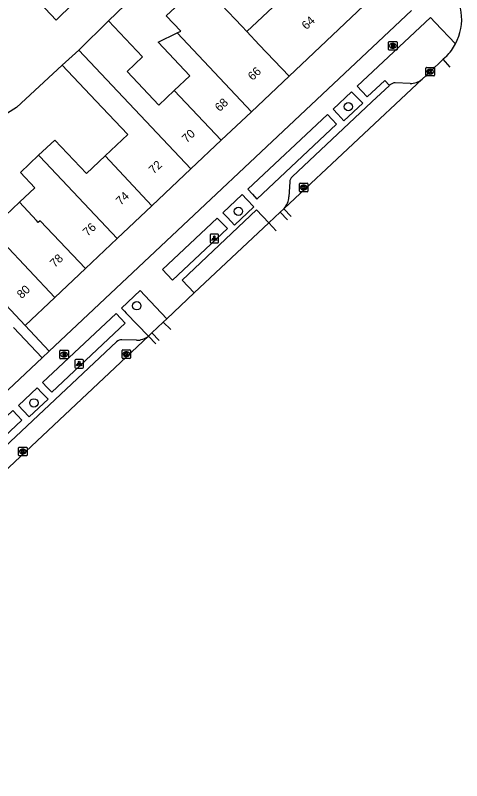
# Model space of a CAD drawing. Extents: x 162347 to 162868, y 381221 to 381813.
# Drawn here: x 162602.8 to 162655.1, y 381237 to 381326.8 of the extents above; entities that cross this region are included whole.
import ezdxf

# ---------------------------------------------------------------- set-up
doc = ezdxf.new("R2010")
doc.units = 0
for name, color, linetype in [('IMGEO_Boom', 7, 'Continuous'), ('IMGEO_Brandkraan', 7, 'Continuous'), ('IMGEO_Kolk', 7, 'Continuous'), ('IMGEO_Lichtpunt', 7, 'Continuous'), ('IMGEO_Pand', 7, 'Continuous'), ('IMGEO_Pand_nummerreeks', 7, 'Continuous'), ('IMGEO_Pand_vergunning_verleend', 7, 'Continuous'), ('IMGEO_Parkeervlak_open', 7, 'Continuous'), ('IMGEO_Rijbaan_lokaal_gesloten', 7, 'Continuous'), ('IMGEO_Rijbaan_lokaal_open', 7, 'Continuous'), ('IMGEO_Voetpad_open', 7, 'Continuous')]:
    doc.layers.add(name, color=color, linetype=linetype)

msp = doc.modelspace()

# ---------------------------------------------------------------- linework, layer by layer
at = {"layer": 'IMGEO_Boom'}
for centre in [(162641.839, 381316.04), (162628.943, 381303.772), (162617.021, 381292.697), (162604.944, 381281.303)]:
    msp.add_circle(centre, 0.489, dxfattribs=at)
at = {"layer": 'IMGEO_Brandkraan'}
for p, q in [((162646.551, 381322.756), (162646.551, 381323.608)), ((162646.626, 381323.682), (162647.478, 381323.682)), ((162647.039, 381323.462), (162647.064, 381323.462)), ((162647.552, 381323.608), (162647.552, 381322.756)), ((162647.478, 381322.682), (162646.626, 381322.682)), ((162647.062, 381322.902), (162647.037, 381322.902)), ((162607.99, 381286.551), (162607.99, 381287.403)), ((162608.065, 381287.477), (162608.917, 381287.477)), ((162608.478, 381287.257), (162608.503, 381287.257)), ((162608.991, 381287.403), (162608.991, 381286.551)), ((162608.917, 381286.477), (162608.065, 381286.477)), ((162608.501, 381286.697), (162608.476, 381286.697))]:
    msp.add_line(p, q, dxfattribs=at)
for points in [[(162646.551, 381322.756), (162646.551, 381323.608)], [(162646.626, 381323.682), (162647.478, 381323.682)], [(162646.899, 381323.382), (162646.899, 381322.982), (162647.112, 381322.982)], [(162647.13, 381323.382), (162646.899, 381323.382)], [(162647.078, 381323.301), (162647.024, 381323.301), (162647.024, 381323.225)], [(162647.024, 381323.225), (162647.077, 381323.225)], [(162647.086, 381323.149), (162647.024, 381323.149), (162647.024, 381323.068)], [(162647.552, 381323.608), (162647.552, 381322.756)], [(162647.478, 381322.682), (162646.626, 381322.682)], [(162647.024, 381323.068), (162647.086, 381323.068)], [(162607.99, 381286.551), (162607.99, 381287.403)], [(162608.065, 381287.477), (162608.917, 381287.477)], [(162608.338, 381287.177), (162608.338, 381286.777), (162608.551, 381286.777)], [(162608.569, 381287.177), (162608.338, 381287.177)], [(162608.991, 381287.403), (162608.991, 381286.551)], [(162608.917, 381286.477), (162608.065, 381286.477)], [(162608.517, 381287.096), (162608.463, 381287.096), (162608.463, 381287.02)], [(162608.463, 381287.02), (162608.516, 381287.02)], [(162608.525, 381286.944), (162608.463, 381286.944), (162608.463, 381286.863)], [(162608.463, 381286.863), (162608.525, 381286.863)]]:
    msp.add_lwpolyline(points, dxfattribs=at)
for centre, radius, start, end in [((162646.628, 381323.606), 0.0765, 91.55205, 178.44795), ((162646.628, 381323.606), 0.0765, 91.55205, 178.44795), ((162647.079, 381323.263), 0.0379, 267.82845, 90.93552), ((162647.087, 381323.108), 0.0404, 269.87594, 90.50774), ((162647.134, 381323.237), 0.145, 59.4692, 91.53667), ((162647.159, 381323.284), 0.0922, 285.51372, 58.15012), ((162647.164, 381323.092), 0.105, 301.31148, 78.98903), ((162647.476, 381323.606), 0.0765, 1.55205, 88.44795), ((162647.476, 381323.606), 0.0765, 1.55205, 88.44795), ((162646.628, 381322.758), 0.0765, 181.55205, 268.44795), ((162646.628, 381322.758), 0.0765, 181.55205, 268.44795), ((162647.118, 381323.233), 0.251, 268.66757, 293.53466), ((162647.476, 381322.758), 0.0765, 271.55205, 358.44795), ((162647.476, 381322.758), 0.0765, 271.55205, 358.44795), ((162608.067, 381287.401), 0.0765, 91.55205, 178.44795), ((162608.067, 381287.401), 0.0765, 91.55205, 178.44795), ((162608.573, 381287.032), 0.145, 59.4692, 91.53667), ((162608.915, 381287.401), 0.0765, 1.55205, 88.44795), ((162608.915, 381287.401), 0.0765, 1.55205, 88.44795), ((162608.067, 381286.553), 0.0765, 181.55205, 268.44795), ((162608.067, 381286.553), 0.0765, 181.55205, 268.44795), ((162608.518, 381287.058), 0.0379, 267.82845, 90.93552), ((162608.526, 381286.903), 0.0404, 269.87594, 90.50774), ((162608.557, 381287.028), 0.251, 268.66757, 293.53466), ((162608.598, 381287.079), 0.0922, 285.51372, 58.15012), ((162608.603, 381286.887), 0.105, 301.31148, 78.98903), ((162608.915, 381286.553), 0.0765, 271.55205, 358.44795), ((162608.915, 381286.553), 0.0765, 271.55205, 358.44795)]:
    msp.add_arc(centre, radius, start, end, dxfattribs=at)
for centre, major_axis, ratio, start_param, end_param in [((162647.038, 381323.182), (-0.387, 0.002), 0.722429, 4.712389, 7.853982), ((162647.063, 381323.182), (-0.39, 0.002), 0.717154, 1.570796, 4.712389), ((162608.477, 381286.977), (-0.387, 0.002), 0.722429, 4.712389, 7.853982), ((162608.502, 381286.977), (-0.39, 0.002), 0.717154, 1.570796, 4.712389)]:
    msp.add_ellipse(centre, major_axis=major_axis, ratio=ratio, start_param=start_param, end_param=end_param, dxfattribs=at)
at = {"layer": 'IMGEO_Kolk'}
for p, q in [((162650.934, 381319.721), (162650.934, 381320.573)), ((162651.009, 381320.647), (162651.861, 381320.647)), ((162651.422, 381320.427), (162651.447, 381320.427)), ((162651.935, 381320.573), (162651.935, 381319.721)), ((162651.861, 381319.647), (162651.009, 381319.647)), ((162651.445, 381319.867), (162651.42, 381319.867)), ((162636.099, 381306.141), (162636.099, 381306.993)), ((162636.174, 381307.067), (162637.026, 381307.067)), ((162637.1, 381306.993), (162637.1, 381306.141)), ((162637.026, 381306.067), (162636.174, 381306.067)), ((162636.61, 381306.287), (162636.585, 381306.287)), ((162636.587, 381306.847), (162636.612, 381306.847)), ((162615.297, 381286.599), (162615.297, 381287.451)), ((162615.372, 381287.525), (162616.224, 381287.525)), ((162615.785, 381287.305), (162615.81, 381287.305)), ((162616.298, 381287.451), (162616.298, 381286.599)), ((162616.224, 381286.525), (162615.372, 381286.525)), ((162615.808, 381286.745), (162615.783, 381286.745)), ((162603.157, 381275.168), (162603.157, 381276.02)), ((162603.232, 381276.094), (162604.084, 381276.094)), ((162603.645, 381275.874), (162603.67, 381275.874)), ((162604.158, 381276.02), (162604.158, 381275.168)), ((162604.084, 381275.094), (162603.232, 381275.094)), ((162603.668, 381275.314), (162603.643, 381275.314))]:
    msp.add_line(p, q, dxfattribs=at)
for points in [[(162650.934, 381319.721), (162650.934, 381320.573)], [(162651.009, 381320.647), (162651.861, 381320.647)], [(162651.935, 381320.573), (162651.935, 381319.721)], [(162651.861, 381319.647), (162651.009, 381319.647)], [(162651.255, 381320.347), (162651.378, 381320.347), (162651.378, 381320.196), (162651.508, 381320.347), (162651.672, 381320.347), (162651.526, 381320.196), (162651.679, 381319.947), (162651.527, 381319.947), (162651.442, 381320.111), (162651.378, 381320.044), (162651.378, 381319.947), (162651.255, 381319.947), (162651.255, 381320.347)], [(162636.099, 381306.141), (162636.099, 381306.993)], [(162636.174, 381307.067), (162637.026, 381307.067)], [(162637.1, 381306.993), (162637.1, 381306.141)], [(162637.026, 381306.067), (162636.174, 381306.067)], [(162636.42, 381306.767), (162636.543, 381306.767), (162636.543, 381306.616), (162636.673, 381306.767), (162636.837, 381306.767), (162636.691, 381306.616), (162636.844, 381306.367), (162636.692, 381306.367), (162636.607, 381306.531), (162636.543, 381306.464), (162636.543, 381306.367), (162636.42, 381306.367), (162636.42, 381306.767)], [(162615.297, 381286.599), (162615.297, 381287.451)], [(162615.372, 381287.525), (162616.224, 381287.525)], [(162615.618, 381287.225), (162615.741, 381287.225), (162615.741, 381287.074), (162615.871, 381287.225), (162616.035, 381287.225), (162615.889, 381287.074), (162616.042, 381286.825), (162615.89, 381286.825), (162615.805, 381286.989), (162615.741, 381286.922), (162615.741, 381286.825), (162615.618, 381286.825), (162615.618, 381287.225)], [(162616.298, 381287.451), (162616.298, 381286.599)], [(162616.224, 381286.525), (162615.372, 381286.525)], [(162603.157, 381275.168), (162603.157, 381276.02)], [(162603.232, 381276.094), (162604.084, 381276.094)], [(162603.478, 381275.794), (162603.601, 381275.794), (162603.601, 381275.643), (162603.731, 381275.794), (162603.895, 381275.794), (162603.749, 381275.643), (162603.902, 381275.394), (162603.75, 381275.394), (162603.665, 381275.558), (162603.601, 381275.491), (162603.601, 381275.394), (162603.478, 381275.394), (162603.478, 381275.794)], [(162604.158, 381276.02), (162604.158, 381275.168)], [(162604.084, 381275.094), (162603.232, 381275.094)]]:
    msp.add_lwpolyline(points, dxfattribs=at)
for centre, start, end in [((162651.011, 381320.571), 91.55205, 178.44795), ((162651.011, 381320.571), 91.55205, 178.44795), ((162651.859, 381320.571), 1.55205, 88.44795), ((162651.859, 381320.571), 1.55205, 88.44795), ((162651.011, 381319.723), 181.55205, 268.44795), ((162651.011, 381319.723), 181.55205, 268.44795), ((162651.859, 381319.723), 271.55205, 358.44795), ((162651.859, 381319.723), 271.55205, 358.44795), ((162636.176, 381306.991), 91.55205, 178.44795), ((162636.176, 381306.991), 91.55205, 178.44795), ((162637.024, 381306.991), 1.55205, 88.44795), ((162637.024, 381306.991), 1.55205, 88.44795), ((162636.176, 381306.143), 181.55205, 268.44795), ((162636.176, 381306.143), 181.55205, 268.44795), ((162637.024, 381306.143), 271.55205, 358.44795), ((162637.024, 381306.143), 271.55205, 358.44795), ((162615.374, 381287.449), 91.55205, 178.44795), ((162615.374, 381287.449), 91.55205, 178.44795), ((162616.222, 381287.449), 1.55205, 88.44795), ((162616.222, 381287.449), 1.55205, 88.44795), ((162615.374, 381286.601), 181.55205, 268.44795), ((162615.374, 381286.601), 181.55205, 268.44795), ((162616.222, 381286.601), 271.55205, 358.44795), ((162616.222, 381286.601), 271.55205, 358.44795), ((162603.234, 381276.018), 91.55205, 178.44795), ((162603.234, 381276.018), 91.55205, 178.44795), ((162604.082, 381276.018), 1.55205, 88.44795), ((162604.082, 381276.018), 1.55205, 88.44795), ((162603.234, 381275.17), 181.55205, 268.44795), ((162603.234, 381275.17), 181.55205, 268.44795), ((162604.082, 381275.17), 271.55205, 358.44795), ((162604.082, 381275.17), 271.55205, 358.44795)]:
    msp.add_arc(centre, 0.0765, start, end, dxfattribs=at)
for centre, major_axis, ratio, start_param, end_param in [((162651.421, 381320.147), (-0.387, 0.002), 0.722429, 4.712389, 7.853982), ((162651.446, 381320.147), (-0.39, 0.002), 0.717154, 1.570796, 4.712389), ((162636.586, 381306.567), (-0.387, 0.002), 0.722429, 4.712389, 7.853982), ((162636.611, 381306.567), (-0.39, 0.002), 0.717154, 1.570796, 4.712389), ((162615.784, 381287.025), (-0.387, 0.002), 0.722429, 4.712389, 7.853982), ((162615.809, 381287.025), (-0.39, 0.002), 0.717154, 1.570796, 4.712389), ((162603.644, 381275.594), (-0.387, 0.002), 0.722429, 4.712389, 7.853982), ((162603.669, 381275.594), (-0.39, 0.002), 0.717154, 1.570796, 4.712389)]:
    msp.add_ellipse(centre, major_axis=major_axis, ratio=ratio, start_param=start_param, end_param=end_param, dxfattribs=at)
at = {"layer": 'IMGEO_Lichtpunt'}
for p, q in [((162625.621, 381300.984), (162625.621, 381300.177)), ((162625.621, 381300.984), (162625.621, 381300.177)), ((162626.523, 381301.079), (162625.715, 381301.079)), ((162626.523, 381301.079), (162625.715, 381301.079)), ((162626.617, 381300.177), (162626.617, 381300.984)), ((162626.617, 381300.177), (162626.617, 381300.984)), ((162625.715, 381300.083), (162626.523, 381300.083)), ((162625.715, 381300.083), (162626.523, 381300.083)), ((162609.769, 381286.292), (162609.769, 381285.485)), ((162609.769, 381286.292), (162609.769, 381285.485)), ((162610.671, 381286.387), (162609.863, 381286.387)), ((162610.671, 381286.387), (162609.863, 381286.387)), ((162610.765, 381285.485), (162610.765, 381286.292)), ((162610.765, 381285.485), (162610.765, 381286.292)), ((162609.863, 381285.391), (162610.671, 381285.391)), ((162609.863, 381285.391), (162610.671, 381285.391))]:
    msp.add_line(p, q, dxfattribs=at)
for points in [[(162625.995, 381300.648), (162626.034, 381300.62), (162625.846, 381300.358), (162625.808, 381300.385), (162625.995, 381300.648)], [(162626.207, 381300.62), (162626.245, 381300.647), (162626.432, 381300.385), (162626.393, 381300.357), (162626.207, 381300.62)], [(162626.097, 381300.6), (162626.144, 381300.6), (162626.144, 381300.278), (162626.097, 381300.278), (162626.097, 381300.6)], [(162610.143, 381285.956), (162610.182, 381285.928), (162609.994, 381285.666), (162609.956, 381285.693), (162610.143, 381285.956)], [(162610.245, 381285.908), (162610.292, 381285.908), (162610.292, 381285.586), (162610.245, 381285.586), (162610.245, 381285.908)], [(162610.355, 381285.928), (162610.393, 381285.955), (162610.58, 381285.693), (162610.541, 381285.665), (162610.355, 381285.928)]]:
    msp.add_lwpolyline(points, dxfattribs=at)
for centre in [(162626.12, 381300.782), (162610.268, 381286.09)]:
    msp.add_circle(centre, 0.0994, dxfattribs=at)
for centre, start, end in [((162625.715, 381300.984), 90, 180), ((162625.715, 381300.984), 90, 180), ((162626.523, 381300.984), 0, 90), ((162626.523, 381300.984), 0, 90), ((162625.715, 381300.177), 180, 270), ((162625.715, 381300.177), 180, 270), ((162626.523, 381300.177), 270, 0), ((162626.523, 381300.177), 270, 360), ((162609.863, 381286.292), 90, 180), ((162609.863, 381286.292), 90, 180), ((162610.671, 381286.292), 0, 90), ((162610.671, 381286.292), 0, 90), ((162609.863, 381285.485), 180, 270), ((162609.863, 381285.485), 180, 270), ((162610.671, 381285.485), 270, 0), ((162610.671, 381285.485), 270, 360)]:
    msp.add_arc(centre, 0.0946, start, end, dxfattribs=at)
at = {"layer": 'IMGEO_Pand'}
for points in [[(162629.938, 381324.841), (162632.97, 381327.703), (162633.243, 381329.819), (162626.751, 381330.658), (162626.959, 381332.52), (162627.514, 381337.489), (162634.853, 381336.669), (162636.515, 381336.483), (162636.272, 381334.735), (162638.163, 381332.6), (162641.264, 381332.167), (162643.71, 381329.594), (162643.635, 381327.873), (162634.883, 381319.61)], [(162621.767, 381324.685), (162622.173, 381324.883), (162620.476, 381326.68), (162624.56, 381330.536), (162629.33, 381325.484), (162629.938, 381324.841)], [(162613.703, 381326.117), (162610.208, 381322.688)], [(162613.703, 381326.117), (162617.694, 381321.891), (162615.885, 381320.183), (162619.616, 381316.231), (162621.426, 381317.94)], [(162621.426, 381317.94), (162623.239, 381319.652), (162619.521, 381323.59), (162621.767, 381324.685)], [(162621.767, 381324.685), (162630.482, 381315.455)], [(162634.883, 381319.61), (162631.379, 381323.314), (162629.938, 381324.841)], [(162610.208, 381322.688), (162608.277, 381320.913)], [(162610.208, 381322.688), (162614.134, 381318.53), (162623.374, 381308.744)], [(162613.297, 381310.265), (162615.957, 381312.776), (162612.226, 381316.728), (162608.277, 381320.913)], [(162634.883, 381319.61), (162630.482, 381315.455)], [(162621.426, 381317.94), (162626.934, 381312.105)], [(162630.482, 381315.455), (162626.934, 381312.105)], [(162605.494, 381310.337), (162607.392, 381312.129), (162611.106, 381308.196), (162613.297, 381310.265)], [(162626.934, 381312.105), (162623.374, 381308.744)], [(162603.276, 381304.83), (162605.065, 381306.52), (162603.362, 381308.324), (162605.494, 381310.337)], [(162605.494, 381310.337), (162605.631, 381310.186), (162614.714, 381300.568)], [(162613.297, 381310.265), (162618.804, 381304.429)], [(162623.374, 381308.744), (162618.804, 381304.429)], [(162598.154, 381303.494), (162599.868, 381305.112), (162601.615, 381303.262), (162603.276, 381304.83)], [(162610.986, 381297.048), (162605.679, 381302.669), (162605.456, 381302.458), (162605.252, 381302.68), (162603.276, 381304.83)], [(162618.804, 381304.429), (162614.714, 381300.568)], [(162598.154, 381303.494), (162598.332, 381303.294), (162607.414, 381293.676)], [(162614.714, 381300.568), (162610.986, 381297.048)], [(162610.986, 381297.048), (162607.414, 381293.676)], [(162598.479, 381296.126), (162600.481, 381294.006), (162603.913, 381290.37)], [(162607.414, 381293.676), (162603.913, 381290.37)]]:
    msp.add_lwpolyline(points, dxfattribs=at)
at = {"layer": 'IMGEO_Pand_vergunning_verleend'}
msp.add_lwpolyline([(162603.052, 381331.009), (162603.77, 381331.681), (162613.666, 381340.953), (162618.167, 381336.158), (162608.281, 381326.876), (162607.559, 381326.199), (162603.052, 381331.009)], dxfattribs=at)
at = {"layer": 'IMGEO_Parkeervlak_open'}
for points in [[(162649.085, 381318.772), (162647.341, 381318.826)], [(162646.728, 381318.584), (162646.667, 381318.527)]]:
    msp.add_lwpolyline(points, dxfattribs=at)
for centre, radius, start, end in [((162647.287, 381318.065), 0.763, 85.95511, 137.1311), ((162649.197, 381320.726), 1.957, 266.70829, 311.09283)]:
    msp.add_arc(centre, radius, start, end, dxfattribs=at)
at = {"layer": 'IMGEO_Rijbaan_lokaal_gesloten'}
for points in [[(162652.983, 381321.602), (162651.435, 381320.147), (162650.484, 381319.251)], [(162653.774, 381320.694), (162652.983, 381321.602)], [(162650.484, 381319.251), (162634.298, 381304.099)], [(162634.298, 381304.099), (162634.271, 381304.074)], [(162634.271, 381304.074), (162635.132, 381303.165)], [(162632.497, 381302.404), (162623.772, 381294.193)], [(162632.497, 381302.404), (162633.362, 381301.5)], [(162623.772, 381294.193), (162620.553, 381291.162)], [(162620.553, 381291.162), (162620.131, 381290.766)], [(162621.016, 381289.891), (162620.131, 381290.766)], [(162618.404, 381289.14), (162564.022, 381238.062), (162562.871, 381236.993)], [(162619.267, 381288.247), (162618.404, 381289.14)]]:
    msp.add_lwpolyline(points, dxfattribs=at)
at = {"layer": 'IMGEO_Rijbaan_lokaal_open'}
for points in [[(162653.341, 381321.938), (162652.983, 381321.602)], [(162633.847, 381303.674), (162632.524, 381302.429)], [(162634.271, 381304.074), (162633.847, 381303.674)], [(162634.718, 381302.775), (162633.847, 381303.674)], [(162632.524, 381302.429), (162632.497, 381302.404)], [(162620.131, 381290.766), (162618.802, 381289.515)], [(162618.802, 381289.515), (162618.404, 381289.14)], [(162619.656, 381288.613), (162618.802, 381289.515)]]:
    msp.add_lwpolyline(points, dxfattribs=at)
for centre, radius, start, end in [((162648.834, 381326.349), 6.306, 332.11689, 41.86905), ((162648.797, 381326.375), 6.351, 315.68485, 332.06956)]:
    msp.add_arc(centre, radius, start, end, dxfattribs=at)
at = {"layer": 'IMGEO_Voetpad_open'}
for points in [[(162630.047, 381341.818), (162613.703, 381326.117)], [(162606.75, 381287.36), (162649.241, 381327.313)], [(162654.408, 381323.4), (162652.04, 381325.932), (162651.494, 381326.516), (162642.884, 381318.432), (162643.43, 381317.847), (162644.045, 381317.188), (162646.11, 381319.125), (162646.667, 381318.527)], [(162608.277, 381320.913), (162602.909, 381315.953), (162601.13, 381314.823)], [(162646.667, 381318.527), (162644.602, 381316.591), (162635.242, 381307.816)], [(162643.53, 381316.435), (162642.778, 381317.219), (162642.225, 381317.797), (162640.053, 381315.737), (162640.598, 381315.151), (162641.328, 381314.366), (162643.53, 381316.435)], [(162640.462, 381313.982), (162639.933, 381314.552), (162639.389, 381315.138), (162630.06, 381306.349), (162630.606, 381305.765), (162631.123, 381305.212), (162640.462, 381313.982)], [(162634.963, 381307.225), (162634.878, 381305.461)], [(162630.765, 381304.282), (162629.938, 381305.157), (162629.389, 381305.739), (162627.114, 381303.609), (162627.662, 381303.026), (162628.5, 381302.136), (162630.765, 381304.282)], [(162623.772, 381294.193), (162622.34, 381295.703), (162631.082, 381303.942), (162632.524, 381302.429)], [(162627.657, 381301.746), (162627.016, 381302.402), (162626.457, 381302.974), (162620.048, 381296.945), (162620.599, 381296.365), (162621.227, 381295.704), (162627.657, 381301.746)], [(162620.553, 381291.162), (162617.982, 381293.886), (162617.433, 381294.468), (162615.241, 381292.424), (162615.575, 381292.068), (162615.792, 381291.844), (162618.404, 381289.14)], [(162615.655, 381290.664), (162615.149, 381291.194), (162614.597, 381291.773), (162605.974, 381283.698), (162606.526, 381283.119), (162607.057, 381282.563), (162615.655, 381290.664)], [(162605.911, 381286.571), (162602.559, 381290.128)], [(162603.913, 381290.37), (162606.75, 381287.36)], [(162614.652, 381288.47), (162564.751, 381241.574), (162563.682, 381240.569)], [(162616.985, 381288.643), (162615.271, 381288.706)], [(162606.75, 381287.36), (162605.911, 381286.571)], [(162546.357, 381239.143), (162548.502, 381238.42), (162551.16, 381237.735), (162553.447, 381237.241), (162605.911, 381286.571)], [(162606.61, 381281.723), (162605.889, 381282.486), (162605.339, 381283.067), (162603.139, 381281.011), (162603.686, 381280.427), (162604.405, 381279.66), (162606.61, 381281.723)], [(162603.55, 381279.273), (162603.031, 381279.815), (162602.477, 381280.392), (162592.788, 381271.311), (162593.332, 381270.724), (162593.855, 381270.159), (162603.55, 381279.273)]]:
    msp.add_lwpolyline(points, dxfattribs=at)
for centre, radius, start, end in [((162635.849, 381307.168), 0.888, 133.13199, 176.32578), ((162632.605, 381305.624), 2.279, 317.98066, 355.88643), ((162616.974, 381290.947), 2.304, 270.26144, 308.34383), ((162615.281, 381287.749), 0.957, 90.61969, 131.12001)]:
    msp.add_arc(centre, radius, start, end, dxfattribs=at)

# ---------------------------------------------------------------- texts
at = {"layer": 'IMGEO_Pand_nummerreeks'}
for s, rotation, p in [('64', 43.35572, (162636.928, 381325.006)), ('66', 43.35572, (162630.616, 381319.047)), ('68', 43.3541, (162626.747, 381315.394)), ('70', 43.3541, (162622.876, 381311.739)), ('72', 43.3541, (162619, 381308.08)), ('74', 43.3541, (162615.132, 381304.427)), ('76', 43.3541, (162611.26, 381300.772)), ('78', 43.3541, (162607.391, 381297.119)), ('80', 43.3541, (162603.52, 381293.464))]:
    msp.add_text(s, height=1, rotation=rotation, dxfattribs=at).set_placement(p)

doc.saveas('drawing.dxf')
